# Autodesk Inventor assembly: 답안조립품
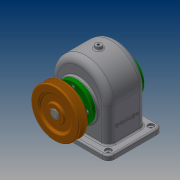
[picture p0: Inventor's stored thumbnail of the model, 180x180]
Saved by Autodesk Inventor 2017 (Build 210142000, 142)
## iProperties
Part Number: 답안조립품
Material: 일반
Document SubType Name: Assembly
Designer: 20
Author: 20
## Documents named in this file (14)
- C:\Users\20\Desktop\480310V1008\답안조립품.iam
- C:\Users\20\Desktop\480310V1008\본체.ipt
- C:\Users\20\Desktop\480310V1008\뒤커버.ipt
- C:\Users\20\Desktop\480310V1008\앞커버.ipt
- C:\Users\20\Desktop\480310V1008\볼트 M4.ipt
- C:\Users\20\Desktop\480310V1008\베어링 6203.ipt
- C:\Users\20\Desktop\480310V1008\축.ipt
- C:\Users\20\Desktop\480310V1008\키 6x6x22.ipt
- C:\Users\20\Desktop\480310V1008\스퍼기어.ipt
- C:\Users\20\Desktop\480310V1008\키 5x5x18.ipt
- C:\Users\20\Desktop\480310V1008\오일 실 28 40 8.ipt
- C:\Users\20\Desktop\480310V1008\부시.ipt
- C:\Users\20\Desktop\480310V1008\멈춤나사 M4.ipt
- C:\Users\20\Desktop\480310V1008\V-벨트풀리.ipt
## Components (1 placed, 1 different names)
1. V-벨트풀리:1 — 플러쉬:2
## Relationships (1: Flush 1)
- 플러쉬:2 [Flush]: V-벨트풀리:1
